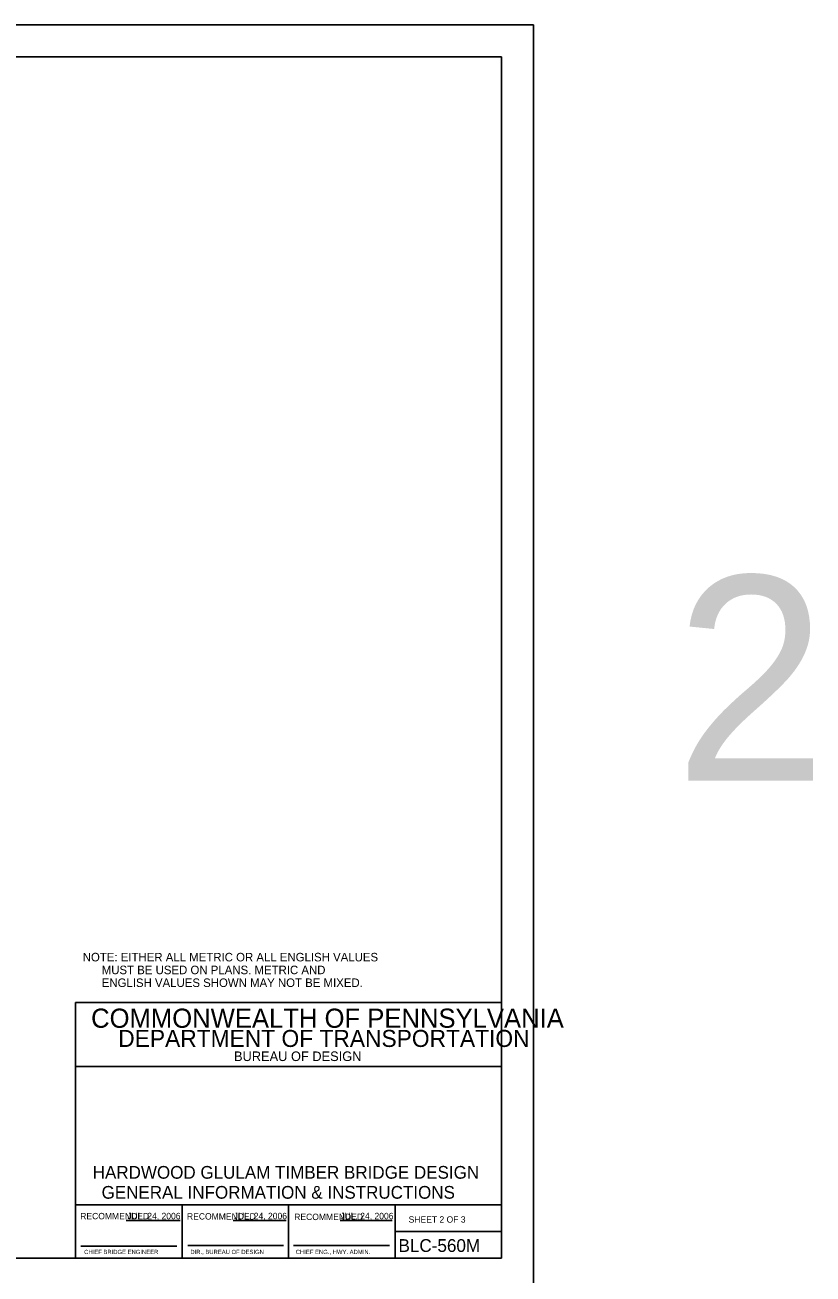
# Model space of a CAD drawing. Extents: x 637594 to 640253, y 297247 to 298527.
# Drawn here: x 639879 to 640249, y 297849 to 298435 of the extents above; entities that cross this region are included whole.
import ezdxf

# ---------------------------------------------------------------- set-up
doc = ezdxf.new("R2010")
doc.units = 0
for name, color, linetype in [('2', 7, 'Continuous'), ('3', 7, 'Continuous'), ('4', 7, 'Continuous'), ('PLT-BNDY', 7, 'Continuous')]:
    doc.layers.add(name, color=color, linetype=linetype)

msp = doc.modelspace()

# ---------------------------------------------------------------- linework, layer by layer
at = {"layer": '2'}
for p, q in [((639316.46, 298420.46), (640102.46, 298420.46)), ((640102.46, 298420.46), (640102.46, 297856.46)), ((640102.46, 297976.46), (639902.46, 297976.46)), ((639902.46, 297976.46), (639902.46, 297856.46)), ((640102.46, 297856.46), (640102.46, 297976.46)), ((640102.46, 297946.46), (639902.46, 297946.46)), ((640102.46, 297881.46), (639902.46, 297881.46)), ((639952.46, 297856.46), (639952.46, 297881.46)), ((640002.46, 297881.46), (640002.46, 297856.46)), ((640052.46, 297881.46), (640052.46, 297856.46)), ((639926.11, 297874.03), (639951.49, 297874.03)), ((639976.38, 297874.03), (640001.27, 297874.03)), ((640026.65, 297874.03), (640051.06, 297874.03)), ((640052.46, 297868.96), (640102.46, 297868.96)), ((639904.96, 297861.96), (639949.96, 297861.96)), ((639955.08, 297862.33), (640000.08, 297862.33)), ((640004.83, 297862.33), (640049.83, 297862.33)), ((640102.46, 297856.46), (639316.46, 297856.46)), ((639902.46, 297856.46), (640102.46, 297856.46))]:
    msp.add_line(p, q, dxfattribs=at)
at = {"layer": 'PLT-BNDY'}
msp.add_lwpolyline([(639276.46, 298435.46), (640117.46, 298435.46), (640117.46, 297841.46), (639276.46, 297841.46)], close=True, dxfattribs=at)

# ---------------------------------------------------------------- texts
at = {"layer": '2'}
for s, height, p in [('COMMONWEALTH OF PENNSYLVANIA', 9, (639909.71, 297964.58)), ('DEPARTMENT OF TRANSPORTATION', 8.0002, (639922.46, 297955.58)), ('BUREAU OF DESIGN', 4.5, (639976.83, 297948.96)), ('HARDWOOD GLULAM TIMBER BRIDGE DESIGN', 5.9716, (639910.48, 297893.71)), ('GENERAL INFORMATION & INSTRUCTIONS', 5.9716, (639914.64, 297884.32)), ('RECOMMENDED', 3, (639904.61, 297874.66)), ('JUL. 24, 2006', 3, (639926.74, 297874.69)), ('RECOMMENDED', 3, (639954.74, 297874.53)), ('JUL. 24, 2006', 3, (639976.74, 297874.69)), ('JUL. 24, 2006', 3, (640026.74, 297874.69)), ('RECOMMENDED', 3, (640005.11, 297874.28)), ('SHEET 2 OF 3', 3, (640058.83, 297873.08)), ('CHIEF BRIDGE ENGINEER', 2.0002, (639906.46, 297858.33)), ('DIR., BUREAU OF DESIGN', 2.0002, (639956.33, 297858.33)), ('CHIEF ENG., HWY. ADMIN.', 2.0002, (640005.83, 297858.33)), ('BLC-560M', 6, (640054.08, 297859.33))]:
    msp.add_text(s, height=height, dxfattribs=at).set_placement(p)
at = {"layer": '3'}
for s, p in [('NOTE: EITHER ALL METRIC OR ALL ENGLISH VALUES', (639905.78, 297995.75)), ('      MUST BE USED ON PLANS. METRIC AND', (639905.78, 297989.74)), ('      ENGLISH VALUES SHOWN MAY NOT BE MIXED.', (639905.78, 297983.73))]:
    msp.add_text(s, height=4.0058, dxfattribs=at).set_placement(p)
at = {"layer": '4'}
msp.add_text('2', height=96, dxfattribs=at).set_placement((640183.81, 298080.69))

doc.saveas('drawing.dxf')
